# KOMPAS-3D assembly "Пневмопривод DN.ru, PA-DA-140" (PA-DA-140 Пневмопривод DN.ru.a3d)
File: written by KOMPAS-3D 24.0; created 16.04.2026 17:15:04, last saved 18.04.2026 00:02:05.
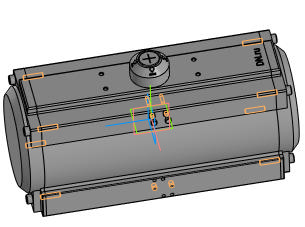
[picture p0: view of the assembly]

Document properties: Автор: DN.ru; Полное имя файла: C:\Работа\PA-DA-х Пневмопривод DN.ru\140\исходные материалы\PA-DA-140 Пневмопривод DN.ru.a3d

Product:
- Component [detail]: Пневмопривод DN.ru  | designation PA-DA-140  | qty 1  | pos. 1  | Масса: 13; Раздел спецификации: Прочие изделия; Примечание: D290-00298; Автор: DN.ru; source file: PA-DA-140 Пневмопривод DN.ru.m3d
- Component [standard]: Болт М5-6gx50 ГОСТ 7805-70  | qty 2  | Масса: 0.008999; Раздел спецификации: Стандартные изделия; Рассекать на разрезах: no
- Component [standard]: Гайка М5-6H ГОСТ 5915-70  | qty 2  | Масса: 0.00144; Раздел спецификации: Стандартные изделия; Рассекать на разрезах: no
- Component [standard]: Винт М8-6gx40 ГОСТ 11738-84  | qty 8  | Масса: 0.02082; Раздел спецификации: Стандартные изделия; Рассекать на разрезах: no
- Part/product: Пневмопривод DN.ru  | designation PA-DA-140
    Масса: 13
    Раздел спецификации: Прочие изделия
    Примечание: D290-00298

Expressions: D290-00298
Referenced files in C:\Работа\PA-DA-х Пневмопривод DN.ru\140\исходные материалы\: PA-DA-140 Пневмопривод DN.ru.m3d
Referenced files in C:\Program Files\ASCON\KOMPAS-3D v24\Libs\PolynomLib\DATA\vault\Methods\Kompas\3D\: PLib_Bolt_1_900.m3d, PLib_Nut_OST92_900.m3d, PLib_Screw_GOST_11738_1500.m3d
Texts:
  PA-DA-140
  Крепежное изделие ГОСТ
  BOSimple***PART:53acba15-081d-1c02-6810-072b309dd366***SHORTLOC:Root±30±20±10±80±10±©{}30±©{BASE}130±30[Нет;Без покрытия;Без указания материала;50;5;8;0,8;-]
  BOSimple***PART:0338bb82-6b79-df62-da33-8b23172f1b3e***SHORTLOC:Root±30±10±20±©{}110±10±50±60[Нет;Без покрытия;Без указания материала;-;5;0,8;8]
  BOSimple***PART:d807d535-b71f-aebb-1123-973396afaf10***SHORTLOC:Root±30±20±10±80±10±GMC90[Нет;Без покрытия;Без указания материала;1,25;-;40;8]
  Программные изделия  и базы данных
  PA-DA-140 Пневмопривод DN.ru
  Болт М5-6gx50 ГОСТ 7805-70 (1)
  hole1
  hole2
  Болт М5-6gx50 ГОСТ 7805-70 (2)
  Гайка М5-6H ГОСТ 5915-70 (1)
  bcut1
  hcut1
  cut1
  Гайка М5-6H ГОСТ 5915-70 (2)
  Винт М8-6gx40 ГОСТ 11738-84 (1)
  Винт М8-6gx40 ГОСТ 11738-84 (2)
  Винт М8-6gx40 ГОСТ 11738-84 (3)
  Винт М8-6gx40 ГОСТ 11738-84 (4)
  Винт М8-6gx40 ГОСТ 11738-84 (5)
  Винт М8-6gx40 ГОСТ 11738-84 (6)
  Винт М8-6gx40 ГОСТ 11738-84 (7)
  Винт М8-6gx40 ГОСТ 11738-84 (8)
  Plane. Начало координат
